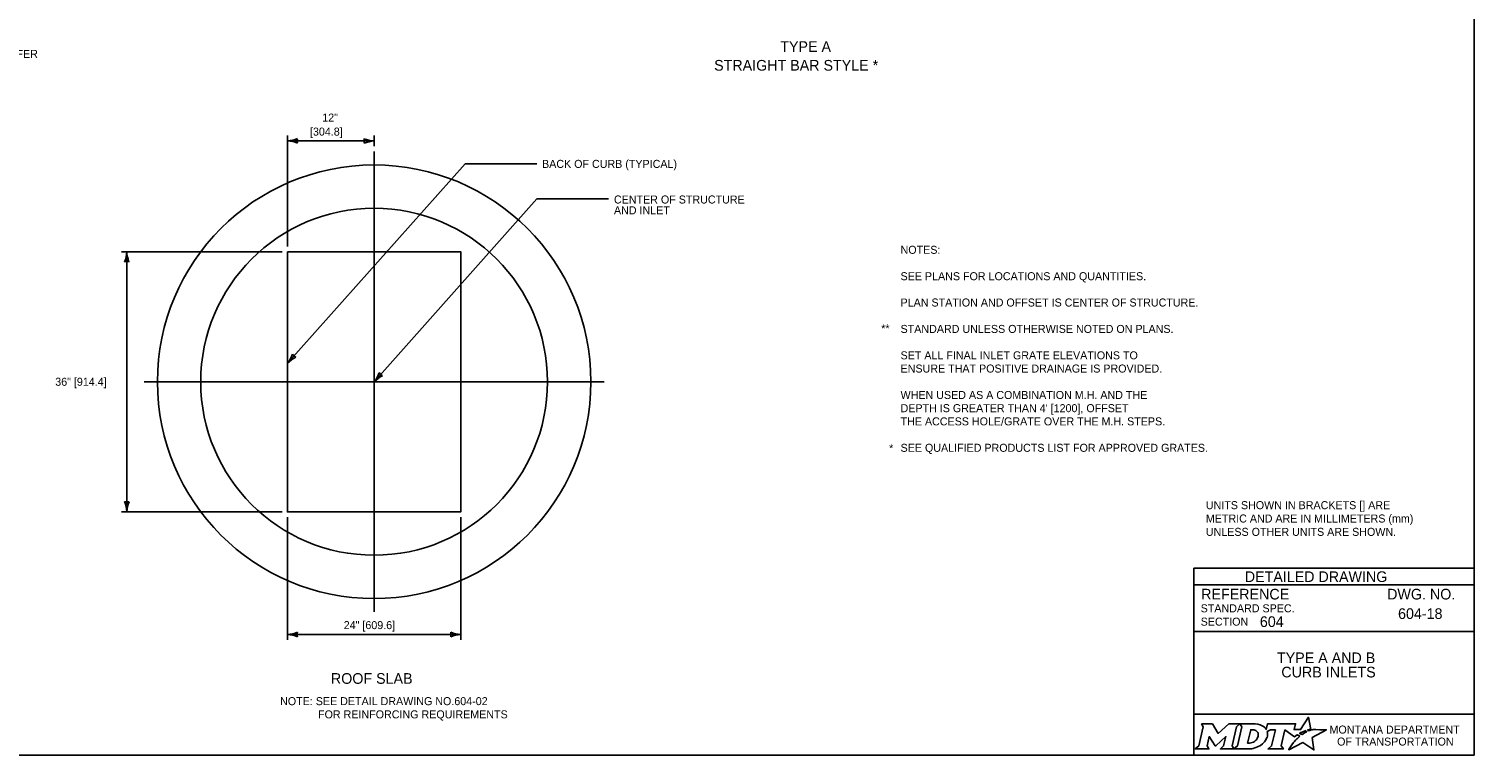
# Model space of a CAD drawing. Extents: x 49991.4 to 50057, y 49987.6 to 50011.4.
# Drawn here: x 50005.91 to 50016.75, y 49987.8 to 49993.24 of the extents above; entities that cross this region are included whole.
import ezdxf

# ---------------------------------------------------------------- set-up
doc = ezdxf.new("R2010")
doc.units = 0
for name, color, linetype in [('Default', 7, 'Continuous'), ('Level 1', 7, 'Continuous'), ('Level 2', 7, 'Continuous'), ('Level 3', 7, 'Continuous'), ('Level 4', 7, 'Continuous'), ('Level 5', 7, 'Continuous')]:
    doc.layers.add(name, color=color, linetype=linetype)

msp = doc.modelspace()

# ---------------------------------------------------------------- linework, layer by layer
at = {"layer": 'Default'}
for points in [[(50015.513, 49987.981), (50015.502, 49987.987), (50015.514, 49987.99), (50015.526, 49987.991), (50015.508, 49988.082), (50015.449, 49987.99), (50015.401, 49987.99), (50015.412, 49988.034), (50015.202, 49988.034), (50015.192, 49987.991), (50015.186, 49988)], [(50014.706, 49988.034), (50014.72, 49988.01), (50014.686, 49987.867), (50014.66, 49987.845), (50014.762, 49987.845), (50014.749, 49987.867), (50014.765, 49987.937), (50014.809, 49987.868), (50014.814, 49987.868), (50014.889, 49987.938), (50014.872, 49987.867), (50014.848, 49987.845), (50014.949, 49987.845), (50014.936, 49987.868), (50014.969, 49988.011)], [(50014.969, 49988.011), (50014.994, 49988.034), (50014.912, 49988.034), (50014.832, 49987.961), (50014.788, 49988.034), (50014.706, 49988.034)], [(50015.108, 49988.034), (50014.994, 49988.034), (50015.009, 49988.011), (50014.975, 49987.867), (50014.949, 49987.845), (50015.06, 49987.845)], [(50015.132, 49987.947), (50015.13, 49987.939), (50015.127, 49987.93), (50015.123, 49987.922), (50015.118, 49987.914), (50015.111, 49987.907), (50015.103, 49987.901), (50015.095, 49987.896), (50015.086, 49987.892), (50015.077, 49987.89), (50015.067, 49987.889), (50015.052, 49987.889), (50015.075, 49987.989), (50015.091, 49987.989), (50015.099, 49987.988), (50015.106, 49987.986), (50015.113, 49987.983), (50015.119, 49987.979), (50015.124, 49987.974), (50015.128, 49987.968), (50015.13, 49987.962), (50015.132, 49987.955), (50015.132, 49987.952), (50015.132, 49987.947)], [(50015.199, 49987.975), (50015.224, 49987.988), (50015.261, 49987.988), (50015.232, 49987.867), (50015.205, 49987.845), (50015.321, 49987.845), (50015.304, 49987.867), (50015.332, 49987.988), (50015.403, 49987.936), (50015.424, 49987.951), (50015.444, 49987.94)], [(50015.388, 49987.884), (50015.373, 49987.86), (50015.368, 49987.852), (50015.362, 49987.844), (50015.36, 49987.839), (50015.465, 49987.893), (50015.549, 49987.838), (50015.536, 49987.93), (50015.643, 49987.989), (50015.594, 49987.989), (50015.564, 49987.99), (50015.543, 49987.99), (50015.536, 49987.989), (50015.531, 49987.987), (50015.523, 49987.985), (50015.513, 49987.981)], [(50015.462, 49987.954), (50015.46, 49987.952), (50015.442, 49987.961), (50015.452, 49987.967), (50015.456, 49987.969), (50015.465, 49987.973), (50015.47, 49987.976), (50015.478, 49987.979), (50015.485, 49987.982), (50015.497, 49987.974), (50015.493, 49987.972), (50015.489, 49987.97), (50015.484, 49987.967), (50015.479, 49987.965), (50015.478, 49987.963), (50015.475, 49987.962), (50015.472, 49987.96), (50015.47, 49987.959), (50015.467, 49987.957), (50015.465, 49987.955), (50015.462, 49987.954)], [(50015.106, 49987.852), (50015.114, 49987.855), (50015.127, 49987.86), (50015.148, 49987.871)], [(50015.402, 49987.9), (50015.402, 49987.9)]]:
    msp.add_lwpolyline(points, dxfattribs=at)
for centre, radius, start, end in [((50015.131, 49987.955), 0.0709, 339.5329, 15.8582), ((50015.087, 49987.973), 0.118, 300.9103, 339.1383)]:
    msp.add_arc(centre, radius, start, end, dxfattribs=at)
for centre, major_axis, ratio, start_param, end_param in [((50015.106, 49987.986), (0.0834, -0.0037), 0.568097, 0.61298, 1.570796), ((50015.161, 49987.994), (0.0361, -0.0295), 0.469099, 1.225588, 1.570796), ((50015.395, 49987.892), (-0.00694, -0.00806), 0.008222, 0, 3.137361), ((50015.412, 49987.911), (-0.0098, -0.0102), 0.016458, 3.141593, 6.279097), ((50015.433, 49987.93), (-0.0112, -0.0097), 0.021651, 3.157348, 6.283185), ((50015.06, 49987.993), (0, 0.148), 0.987302, 3.139398, 3.456847)]:
    msp.add_ellipse(centre, major_axis=major_axis, ratio=ratio, start_param=start_param, end_param=end_param, dxfattribs=at)
at = {"layer": 'Level 1'}
for points in [[(49999.384, 49998.999), (50016.75, 49998.999), (50016.75, 49987.799), (49999.384, 49987.799)], [(50007.853, 49991.572), (50007.853, 49989.622), (50009.153, 49989.622), (50009.153, 49991.572)]]:
    msp.add_lwpolyline(points, close=True, dxfattribs=at)
msp.add_circle((50008.503, 49990.597), 1.625, dxfattribs=at)
at = {"layer": 'Level 3'}
for p, q in [((50007.853, 49991.612), (50007.853, 49992.442)), ((50008.503, 49992.362), (50008.503, 49992.442)), ((50007.853, 49992.402), (50008.503, 49992.402)), ((50007.853, 49990.736), (50009.185, 49992.23)), ((50009.185, 49992.23), (50009.722, 49992.23)), ((50008.503, 49990.597), (50009.724, 49991.967)), ((50009.724, 49991.967), (50010.261, 49991.967)), ((50007.813, 49991.572), (50006.609, 49991.572)), ((50006.649, 49991.572), (50006.649, 49989.622)), ((50007.813, 49989.622), (50006.609, 49989.622)), ((50007.853, 49989.582), (50007.853, 49988.663)), ((50009.153, 49989.582), (50009.153, 49988.663)), ((50007.853, 49988.703), (50009.153, 49988.703))]:
    msp.add_line(p, q, dxfattribs=at)
for centre, radius, start, end in [((50007.842, 49992.635), 0.233, 272.8273, 292.0772), ((50007.981, 49992.402), 0.0548, 162.1388, 197.8612), ((50008.512, 49992.624), 0.222, 247.456, 267.6395), ((50008.375, 49992.402), 0.0548, 342.1388, 17.8612), ((50007.844, 49992.18), 0.222, 67.456, 87.6395), ((50008.515, 49992.169), 0.233, 92.8273, 112.0772), ((50006.426, 49991.581), 0.222, 337.456, 357.6395), ((50006.881, 49991.584), 0.233, 182.8273, 202.0772), ((50006.649, 49991.444), 0.0548, 72.1388, 107.8612), ((50007.672, 49990.882), 0.233, 321.1041, 340.3539), ((50007.938, 49990.832), 0.0548, 210.4156, 246.1379), ((50008.013, 49990.581), 0.222, 115.7328, 135.9163), ((50008.322, 49990.743), 0.233, 321.1041, 340.3539), ((50008.663, 49990.442), 0.222, 115.7328, 135.9163), ((50008.588, 49990.693), 0.0548, 210.4156, 246.1379), ((50006.649, 49989.75), 0.0548, 252.1388, 287.8612), ((50006.416, 49989.611), 0.233, 2.8273, 22.0772), ((50006.871, 49989.613), 0.222, 157.456, 177.6395), ((50007.842, 49988.935), 0.233, 272.8273, 292.0772), ((50007.844, 49988.48), 0.222, 67.456, 87.6395), ((50007.981, 49988.703), 0.0548, 162.1388, 197.8612), ((50009.162, 49988.925), 0.222, 247.456, 267.6395), ((50009.025, 49988.703), 0.0548, 342.1388, 17.8612), ((50009.165, 49988.47), 0.233, 92.8273, 112.0772)]:
    msp.add_arc(centre, radius, start, end, dxfattribs=at)
at = {"layer": 'Level 4'}
msp.add_circle((50008.503, 49990.597), 1.3, dxfattribs=at)
at = {"layer": 'Level 5'}
for p, q in [((50008.503, 49992.322), (50008.503, 49988.872)), ((50006.778, 49990.597), (50010.228, 49990.597)), ((50016.75, 49989.199), (50014.65, 49989.199)), ((50014.65, 49989.199), (50014.65, 49987.799)), ((50016.75, 49989.074), (50014.65, 49989.074)), ((50016.386, 49988.859), (50016.386, 49988.859)), ((50015.144, 49988.799), (50015.144, 49988.799)), ((50016.75, 49988.724), (50014.65, 49988.724)), ((50015.7, 49988.475), (50015.7, 49988.475)), ((50016.75, 49988.106), (50014.65, 49988.106))]:
    msp.add_line(p, q, dxfattribs=at)

# ---------------------------------------------------------------- texts
at = {"layer": 'Default'}
for s, p in [('MONTANA DEPARTMENT', (50015.666, 49987.96)), ('OF TRANSPORTATION', (50015.723, 49987.87))]:
    msp.add_text(s, height=0.06, dxfattribs=at).set_placement(p)
at = {"layer": 'Level 2'}
for s, height, p in [('NEW SIDEWALK OR BUFFER', 0.06, (50004.872, 49993.024)), ('TYPE A', 0.08, (50011.548, 49993.069)), ('STRAIGHT BAR STYLE *', 0.08, (50011.052, 49992.929)), ('12" ', 0.06, (50008.114, 49992.547)), ('[304.8]', 0.06, (50008.022, 49992.442)), ('BACK OF CURB (TYPICAL)', 0.06, (50009.762, 49992.2)), ('NOTES:  ', 0.06, (50012.45, 49991.556)), ('SEE PLANS FOR LOCATIONS AND QUANTITIES.', 0.06, (50012.45, 49991.358)), ('PLAN STATION AND OFFSET IS CENTER OF STRUCTURE.', 0.06, (50012.45, 49991.161)), ('**', 0.06, (50012.305, 49990.967)), ('STANDARD UNLESS OTHERWISE NOTED ON PLANS.', 0.06, (50012.45, 49990.963)), ('SET ALL FINAL INLET GRATE ELEVATIONS TO', 0.06, (50012.45, 49990.765)), ('ENSURE THAT POSITIVE DRAINAGE IS PROVIDED.', 0.06, (50012.45, 49990.666)), ('36" [914.4]', 0.06, (50006.112, 49990.567)), ('WHEN USED AS A COMBINATION M.H. AND THE', 0.06, (50012.45, 49990.468)), ("DEPTH IS GREATER THAN 4' [1200], OFFSET", 0.06, (50012.45, 49990.369)), ('THE ACCESS HOLE/GRATE OVER THE M.H. STEPS.', 0.06, (50012.45, 49990.27)), ('*', 0.06, (50012.364, 49990.069)), ('SEE QUALIFIED PRODUCTS LIST FOR APPROVED GRATES.', 0.06, (50012.45, 49990.072)), ('UNITS SHOWN IN BRACKETS [] ARE ', 0.06, (50014.739, 49989.642)), ('METRIC AND ARE IN MILLIMETERS (mm) ', 0.06, (50014.739, 49989.542)), ('UNLESS OTHER UNITS ARE SHOWN.', 0.06, (50014.739, 49989.442)), ('604', 0.08, (50015.144, 49988.759)), ('604-18', 0.08, (50016.18, 49988.819)), ('24" [609.6]', 0.06, (50008.275, 49988.743)), ('TYPE A AND B ', 0.08, (50015.272, 49988.488)), ('ROOF SLAB', 0.08, (50008.179, 49988.333)), ('CURB INLETS', 0.08, (50015.305, 49988.381)), ('NOTE: SEE DETAIL DRAWING NO.604-02', 0.06, (50007.798, 49988.173)), ('  FOR REINFORCING REQUIREMENTS', 0.06, (50008.038, 49988.074))]:
    msp.add_text(s, height=height, dxfattribs=at).set_placement(p)
for s, p in [('CENTER OF STRUCTURE ', (50010.301, 49991.933)), ('AND INLET', (50010.301, 49991.852))]:
    msp.add_text(s, height=0.06, rotation=360, dxfattribs=at).set_placement(p)
at = {"layer": 'Level 5'}
for s, height, p in [('DETAILED DRAWING', 0.0799, (50015.031, 49989.096)), ('REFERENCE', 0.08, (50014.704, 49988.965)), ('DWG. NO.', 0.08, (50016.098, 49988.965)), ('STANDARD SPEC.', 0.06, (50014.7, 49988.869)), ('SECTION', 0.06, (50014.7, 49988.769))]:
    msp.add_text(s, height=height, dxfattribs=at).set_placement(p)

doc.saveas('drawing.dxf')
